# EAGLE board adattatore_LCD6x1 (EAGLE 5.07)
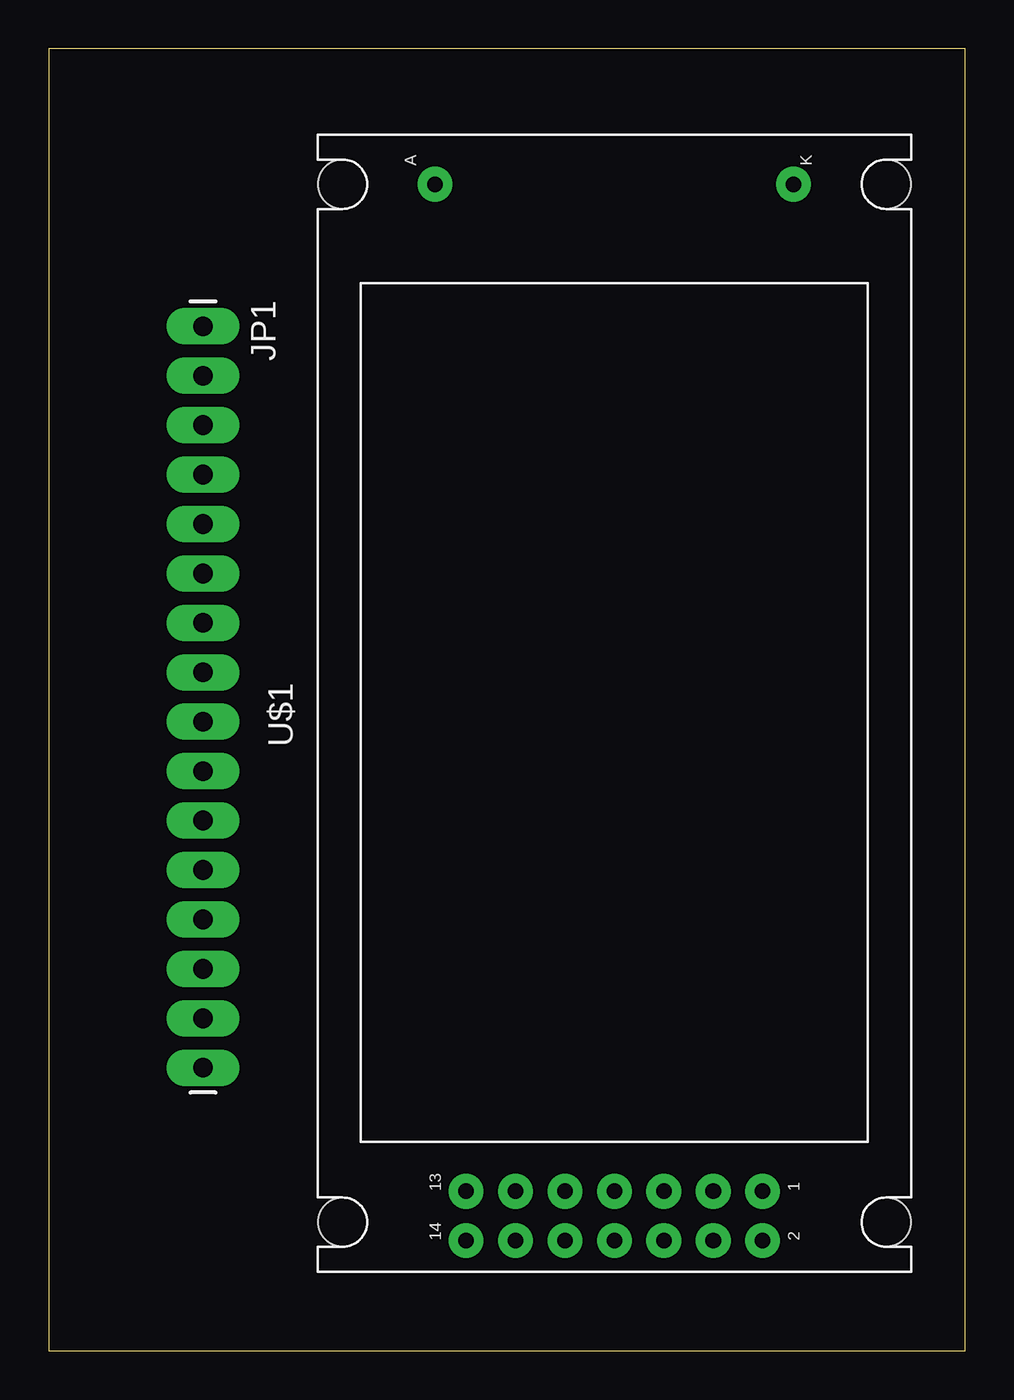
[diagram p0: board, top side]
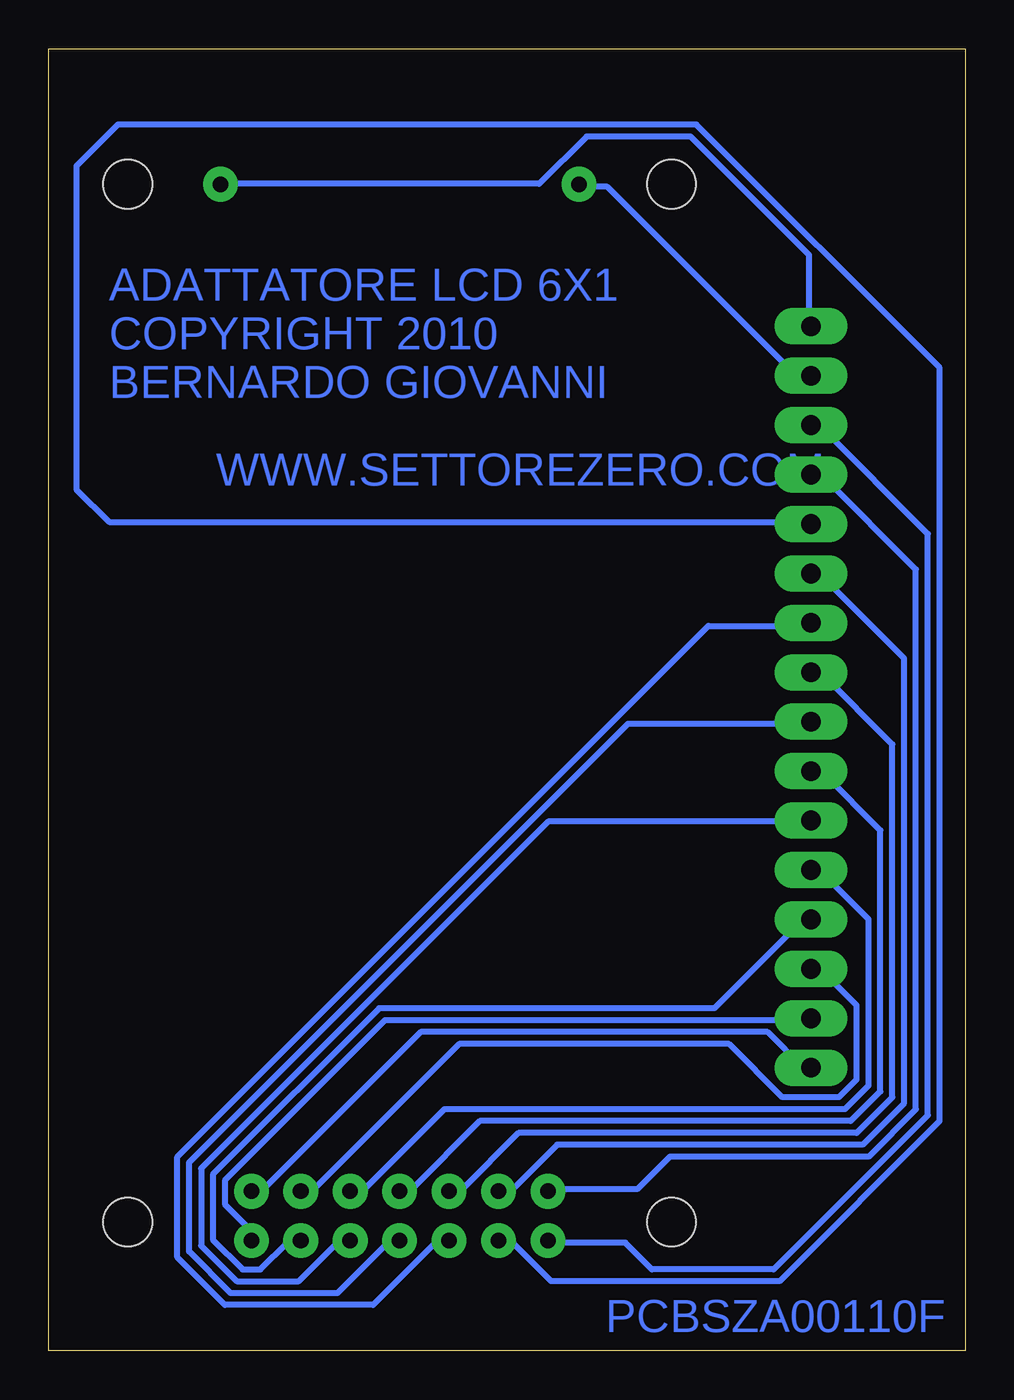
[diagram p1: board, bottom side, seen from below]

Size 47.09 x 66.92 mm. Coordinates in mm from the lower left corner, seen from the top.
Outline: 0,0 47.09,0 47.09,66.92 0,66.92 0,0
Copper layers (1*16): Top 0.035mm / dielectric 1.5mm / Bottom 0.035mm
Design rules "default *": minimum track width 12mil, minimum drill 18mil, track to track 12mil, track to pad 12mil, pad to pad 12mil, via to via 12mil, smd to smd 8mil, copper to edge 40mil, drill to drill 8mil, minimum pad ring 10mil, minimum via ring 8mil, stop-mask expansion 4mil, vias tented up to drill 0mil, thermal gap 10mil

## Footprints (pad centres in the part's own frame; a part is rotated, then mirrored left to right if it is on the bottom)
1X16_LONGPADS = drill 1.016 pad 1.88 long: 1 0,0; 2 2.54,0; 3 5.08,0; 4 7.62,0; 5 10.16,0; 6 12.7,0; 7 15.24,0; 8 17.78,0; 9 20.32,0; 10 22.86,0; 11 25.4,0; 12 27.94,0; 13 30.48,0; 14 33.02,0; 15 35.56,0; 16 38.1,0
LCD6X1 = drill 0.8 pad 1.778 round: 1 3.81,7.62; 2 1.27,7.62; 3 3.81,10.16; 4 1.27,10.16; 5 3.81,12.7; 6 1.27,12.7; 7 3.81,15.24; 8 1.27,15.24; 9 3.81,17.78; 10 1.27,17.78; 11 3.81,20.32; 12 1.27,20.32; 13 3.81,22.86; 14 1.27,22.86; 15 55.562,24.448; 16 55.562,6.032 | hole 2.5: 2.223,1.27; 2.223,29.21; 55.562,29.21; 55.562,1.27

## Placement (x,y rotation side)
JP1  [1X16_LONGPADS]  7.93,52.65 270 top
U$1  LCD6X1  [LCD6X1]  44.3,4.39 90 top
U$2  [INVADER_5_5X4]  41.5,45.96 0 top

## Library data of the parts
JP1 = SparkFun
U$1 U$2 = settorezero

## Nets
N$1: JP1.1 U$1.16
N$2: JP1.2 U$1.15
N$3: JP1.3 U$1.14
N$4: JP1.4 U$1.13
N$5: JP1.5 U$1.12
N$6: JP1.6 U$1.11
N$7: JP1.7 U$1.10
N$8: JP1.8 U$1.9
N$9: JP1.9 U$1.8
N$10: JP1.10 U$1.7
N$11: JP1.11 U$1.6
N$12: JP1.12 U$1.5
N$13: JP1.13 U$1.4
N$14: JP1.14 U$1.3
N$15: JP1.15 U$1.2
N$16: JP1.16 U$1.1

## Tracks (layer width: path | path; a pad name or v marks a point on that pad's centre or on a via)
N$1
  Bottom 0.305: U$1.16 38.2,59.97 21.89,59.97 19.45,62.41 14.12,62.41 8.02,56.31 8.02,52.65 JP1.1
N$2
  Bottom 0.305: U$1.15 19.76,59.82 18.38,59.82 8.78,50.21 8.02,50.21 JP1.2
N$3
  Bottom 0.305: U$1.14 21.43,5.56 17.47,5.56 16.1,4.19 9.85,4.19 1.92,12.11 1.92,41.98 7.41,47.47 7.87,47.47 JP1.3
N$4
  Bottom 0.305: U$1.13 21.43,8.3 16.86,8.3 15.18,9.98 4.97,9.98 2.53,12.42 2.53,40.16 7.26,44.88 7.87,44.88 JP1.4
N$5
  Bottom 0.305: U$1.12 23.87,5.56 23.26,5.56 21.28,3.58 9.54,3.58 1.32,11.81 1.32,50.52 13.81,63.02 43.53,63.02 45.66,60.88 45.66,44.27 43.99,42.59 8.02,42.59 JP1.5
N$6
  Bottom 0.305: U$1.11 23.87,8.3 23.26,8.3 20.98,10.59 5.28,10.59 3.14,12.72 3.14,35.58 7.41,39.85 7.87,39.85 JP1.6
N$7
  Bottom 0.305: U$1.10 26.61,5.56 27.22,5.56 30.42,2.36 38.04,2.36 40.48,4.8 40.48,9.98 13.2,37.26 8.02,37.26 JP1.7
N$8
  Bottom 0.305: U$1.9 26.46,8.3 25.85,8.3 22.96,11.2 5.58,11.2 3.75,13.03 3.75,31.16 7.41,34.82 7.87,34.82 JP1.8
N$9
  Bottom 0.305: U$1.8 29.2,5.56 29.66,5.56 32.25,2.97 37.74,2.97 39.87,5.1 39.87,9.68 17.32,32.23 8.02,32.23 JP1.9
N$10
  Bottom 0.305: U$1.7 29.05,8.3 28.44,8.3 24.94,11.81 5.89,11.81 4.36,13.33 4.36,26.75 7.26,29.64 7.87,29.64 JP1.10
N$11
  Bottom 0.305: U$1.6 31.64,5.56 32.25,5.56 34.23,3.58 37.43,3.58 39.26,5.41 39.26,9.37 21.43,27.2 8.02,27.2 JP1.11
N$12
  Bottom 0.305: U$1.5 31.49,8.3 30.88,8.3 26.77,12.42 6.19,12.42 4.97,13.64 4.97,22.17 7.41,24.61 7.87,24.61 JP1.12
N$13
  Bottom 0.305: U$1.4 34.23,5.56 34.84,5.56 36.22,4.19 37.13,4.19 38.65,5.71 38.65,9.07 30.12,17.6 12.9,17.6 8.48,22.02 8.02,22.02 JP1.13
N$14
  Bottom 0.305: U$1.3 34.08,8.3 33.47,8.3 26,15.77 12.14,15.77 9.39,13.03 6.5,13.03 5.58,13.94 5.58,17.75 7.41,19.58 7.87,19.58 JP1.14
N$15
  Bottom 0.305: U$1.2 36.82,5.71 36.82,6.32 38.04,7.54 38.04,8.76 29.81,16.99 8.02,16.99 JP1.15
N$16
  Bottom 0.305: U$1.1 36.67,8.3 36.06,8.3 27.98,16.38 10.15,16.38 8.33,14.55 8.02,14.55 JP1.16

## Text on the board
Bottom: ADATTATORE LCD 6X1 | COPYRIGHT 2010 | BERNARDO GIOVANNI | WWW.SETTOREZERO.COM | PCBSZA00110F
